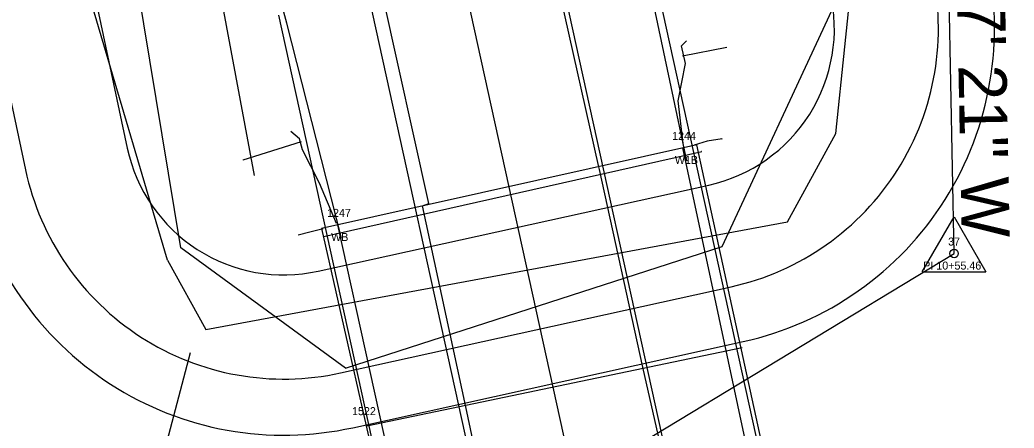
# Model space of a CAD drawing. Extents: x 2519952 to 2531965, y 848341 to 887632.
# Drawn here: x 2525550.6 to 2525674.8, y 850919.3 to 850970.2 of the extents above; entities that cross this region are included whole.
import ezdxf

# ---------------------------------------------------------------- set-up
doc = ezdxf.new("R2010")
doc.units = 0
for name, color, linetype in [('RD_EV_JW', 7, 'Continuous'), ('RD_EX_BldgApp', 7, 'Continuous'), ('RD_EX_BldgApp_txCode', 7, 'Continuous'), ('RD_EX_Bridge', 7, 'Continuous'), ('RD_EX_Conc', 7, 'Continuous'), ('RD_EX_DR_Pipe', 7, 'Continuous'), ('RD_EX_GuardRail', 7, 'Continuous'), ('RD_EX_H2O', 7, 'Continuous'), ('RD_EX_Misc', 7, 'Continuous'), ('RD_EX_Road', 7, 'Continuous'), ('RD_EX_VEG', 7, 'Continuous'), ('RD_HC_Cl', 7, 'Continuous'), ('RD_HC_Data', 7, 'Continuous'), ('RD_HC_txCode', 7, 'Continuous'), ('RD_PD_BCA', 7, 'Continuous'), ('RD_PD_Bridge', 7, 'Continuous'), ('RD_PD_CstnLmt', 7, 'Continuous'), ('RD_PD_DR_ErosCtrl', 7, 'Continuous'), ('RD_PD_Final_TrvlWay', 7, 'Continuous'), ('RD_SMD_Locator', 7, 'Continuous')]:
    doc.layers.add(name, color=color, linetype=linetype)

msp = doc.modelspace()

# ---------------------------------------------------------------- linework, layer by layer
at = {"layer": 'RD_EV_JW'}
for points in [[(2525591.32, 850926.75), (2525570.73, 850941.75), (2525560.7, 851002.49), (2525540.75, 851150.19), (2525528.25, 851203.9), (2525505.08, 851291.34), (2525487.75, 851356.95), (2525470.97, 851403.59), (2525413.82, 851519.63), (2525369.36, 851485.89), (2525324.58, 851439.69)], [(2525591.32, 850926.75), (2525638.37, 850941.92), (2525652.07, 850971.35), (2525633.01, 851029.27), (2525607.97, 851098.28), (2525578.35, 851237.04), (2525560.84, 851309.59), (2525538.79, 851410.02), (2525528.87, 851454.74), (2525557.98, 851458.53), (2525587.45, 851464.47)]]:
    msp.add_lwpolyline(points, dxfattribs=at)
at = {"layer": 'RD_EX_BldgApp'}
for points in [[(2525649.6, 850880.16), (2525641.48, 850916.68), (2525633.46, 850954.22)], [(2525606.83, 850870.63), (2525598.43, 850908.03), (2525590.36, 850944.61)]]:
    msp.add_lwpolyline(points, dxfattribs=at)
at = {"layer": 'RD_EX_Bridge'}
for points in [[(2525605.06, 850870.31), (2525651.35, 850880.55), (2525635.22, 850954.61), (2525588.3, 850944.15), (2525605.06, 850870.31)], [(2525638.35, 850955.37), (2525636.5, 850955.07), (2525634.86, 850954.58)], [(2525588.53, 850944.11), (2525586.86, 850943.7), (2525585.39, 850943.35)]]:
    msp.add_lwpolyline(points, dxfattribs=at)
at = {"layer": 'RD_EX_Conc'}
for points in [[(2525633.49, 850954.79), (2525632.89, 850960.08), (2525633.8, 850964.77), (2525633.27, 850966.96), (2525633.93, 850967.6)], [(2525590.2, 850944.8), (2525588.05, 850949.82), (2525585.96, 850953.99), (2525585.56, 850955.36), (2525584.5, 850956.28)]]:
    msp.add_lwpolyline(points, dxfattribs=at)
at = {"layer": 'RD_EX_DR_Pipe'}
for p, q in [((2525633.42, 850965.69), (2525638.96, 850966.78)), ((2525585.77, 850954.99), (2525578.49, 850952.71))]:
    msp.add_line(p, q, dxfattribs=at)
at = {"layer": 'RD_EX_GuardRail'}
for p, q in [((2525583.99, 850969.79), (2525579.32, 850986.5)), ((2525590.8, 850942.95), (2525583.99, 850969.79))]:
    msp.add_line(p, q, dxfattribs=at)
msp.add_lwpolyline([(2525633.94, 850952.63), (2525628.39, 850978.97), (2525617.95, 851029.61)], dxfattribs=at)
at = {"layer": 'RD_EX_H2O'}
msp.add_line((2525569.06, 850940.22), (2525556.4, 850983.07), dxfattribs=at)
for points in [[(2525569.06, 850940.22), (2525573.85, 850931.56), (2525646.52, 850945.01), (2525652.58, 850956.02), (2525657.08, 850999.33)], [(2525571.91, 850928.64), (2525562.34, 850892.29), (2525495.05, 850852.98), (2525445.02, 850814.74), (2525389.11, 850765.35), (2525390.78, 850735.13), (2525320.16, 850704.48)]]:
    msp.add_lwpolyline(points, dxfattribs=at)
at = {"layer": 'RD_EX_Misc'}
for p, q in [((2525588.61, 850943.18), (2525635.81, 850953.78)), ((2525640.87, 850929.29), (2525593.99, 850919.52))]:
    msp.add_line(p, q, dxfattribs=at)
at = {"layer": 'RD_EX_Road'}
for p, q in [((2525622.93, 850952.03), (2525601.4, 851047.5)), ((2525601.73, 850947.28), (2525580.47, 851042.89)), ((2525623.05, 850951.54), (2525622.93, 850952.03)), ((2525628.46, 850926.86), (2525623.05, 850951.54)), ((2525600.95, 850947.01), (2525601.73, 850947.28)), ((2525606.33, 850921.93), (2525600.95, 850947.01)), ((2525633.95, 850902.66), (2525628.46, 850926.86)), ((2525611.67, 850897.49), (2525606.33, 850921.93))]:
    msp.add_line(p, q, dxfattribs=at)
at = {"layer": 'RD_EX_VEG'}
msp.add_lwpolyline([(2525579.96, 850950.78), (2525563.02, 851041.29), (2525521.77, 851231.67), (2525469.67, 851393.75)], dxfattribs=at)
at = {"layer": 'RD_HC_Cl'}
for p, q in [((2525471.32, 851586.92), (2526027.91, 849059.27)), ((2525667.34, 850941.04), (2525666.26, 850995.82)), ((2525502.2, 850841.35), (2525667.34, 850941.04))]:
    msp.add_line(p, q, dxfattribs=at)
at = {"layer": 'RD_HC_Data'}
for p, q in [((2525663.36, 850938.75), (2525667.34, 850945.63)), ((2525667.34, 850945.63), (2525671.31, 850938.75)), ((2525663.36, 850938.75), (2525671.31, 850938.75))]:
    msp.add_line(p, q, dxfattribs=at)
msp.add_circle((2525667.34, 850941.04), 0.529, dxfattribs=at)
at = {"layer": 'RD_PD_BCA'}
msp.add_lwpolyline([(2525592.21, 850919.31), (2525641, 850930.06)], dxfattribs=at)
for centre, start, end in [((2525632.39, 850969.12), 282.4185, 13.0724), ((2525583.61, 850958.38), 192.0677, 282.4185)]:
    msp.add_arc(centre, 40, start, end, dxfattribs=at)
at = {"layer": 'RD_PD_Bridge'}
for points in [[(2525656.79, 850853.95), (2525628.83, 850980.91)], [(2525582.93, 850970.8), (2525610.88, 850843.85)]]:
    msp.add_lwpolyline(points, dxfattribs=at)
at = {"layer": 'RD_PD_CstnLmt'}
msp.add_line((2525553.67, 851002.76), (2525564.05, 850954.2), dxfattribs=at)
msp.add_lwpolyline([(2525587.91, 850938.84), (2525636.69, 850949.59)], dxfattribs=at)
for centre, start, end in [((2525632.39, 850969.12), 282.4185, 13.0724), ((2525583.61, 850958.38), 192.0677, 282.4185)]:
    msp.add_arc(centre, 20, start, end, dxfattribs=at)
at = {"layer": 'RD_PD_DR_ErosCtrl'}
msp.add_line((2525540.95, 851000.04), (2525551.34, 850951.48), dxfattribs=at)
msp.add_lwpolyline([(2525590.7, 850926.15), (2525639.49, 850936.89)], dxfattribs=at)
for centre, start, end in [((2525632.39, 850969.12), 282.4185, 13.0724), ((2525583.61, 850958.38), 192.0677, 282.4185)]:
    msp.add_arc(centre, 33, start, end, dxfattribs=at)
at = {"layer": 'RD_PD_Final_TrvlWay'}
for p, q in [((2525571.9, 851185.96), (2525846.09, 849940.79)), ((2525548.46, 851180.8), (2525822.65, 849935.63))]:
    msp.add_line(p, q, dxfattribs=at)
at = {"layer": 'RD_SMD_Locator'}
for centre in [(2525583.99, 850969.79), (2525633.93, 850967.6), (2525633.27, 850966.96), (2525638.96, 850966.78), (2525633.42, 850965.69), (2525633.8, 850964.77), (2525632.89, 850960.08), (2525584.5, 850956.28), (2525652.58, 850956.02), (2525585.56, 850955.36), (2525585.77, 850954.99), (2525633.49, 850954.79), (2525634.86, 850954.58), (2525635.22, 850954.61), (2525636.5, 850955.07), (2525638.35, 850955.37), (2525585.96, 850953.99), (2525633.46, 850954.22), (2525635.81, 850953.78), (2525578.49, 850952.71), (2525633.94, 850952.63), (2525622.93, 850952.03), (2525623.05, 850951.54), (2525579.96, 850950.78), (2525588.05, 850949.82), (2525601.73, 850947.28), (2525600.95, 850947.01), (2525590.2, 850944.8), (2525590.36, 850944.61), (2525646.52, 850945.01), (2525586.86, 850943.7), (2525588.3, 850944.15), (2525588.53, 850944.11), (2525585.39, 850943.35), (2525588.61, 850943.18), (2525590.8, 850942.95), (2525570.73, 850941.75), (2525638.37, 850941.92), (2525667.34, 850941.04), (2525569.06, 850940.22), (2525569.06, 850940.22), (2525573.85, 850931.56), (2525571.91, 850928.64), (2525640.87, 850929.29), (2525591.32, 850926.75), (2525591.32, 850926.75), (2525628.46, 850926.86), (2525606.33, 850921.93), (2525593.48, 850919.88), (2525593.99, 850919.52)]:
    msp.add_circle(centre, 0.001, dxfattribs=at)

# ---------------------------------------------------------------- texts
at = {"layer": 'RD_EX_BldgApp_txCode'}
for s, p in [('1244', (2525632.12, 850955.22)), ('W1B', (2525632.46, 850952.22)), ('1247', (2525589.01, 850945.61)), ('WB', (2525589.52, 850942.61)), ('1522', (2525592.13, 850920.88))]:
    msp.add_text(s, height=1, dxfattribs=at).set_placement(p)
at = {"layer": 'RD_HC_Data'}
msp.add_text('N 1%%d 07\' 21" W', height=6, rotation=271.1226, dxfattribs=at).set_placement((2525667.28, 850995.16))
at = {"layer": 'RD_HC_txCode'}
for s, p in [('37', (2525666.6, 850942.04)), ('PI 10+55.46', (2525663.49, 850939.04))]:
    msp.add_text(s, height=1, dxfattribs=at).set_placement(p)

doc.saveas('drawing.dxf')
